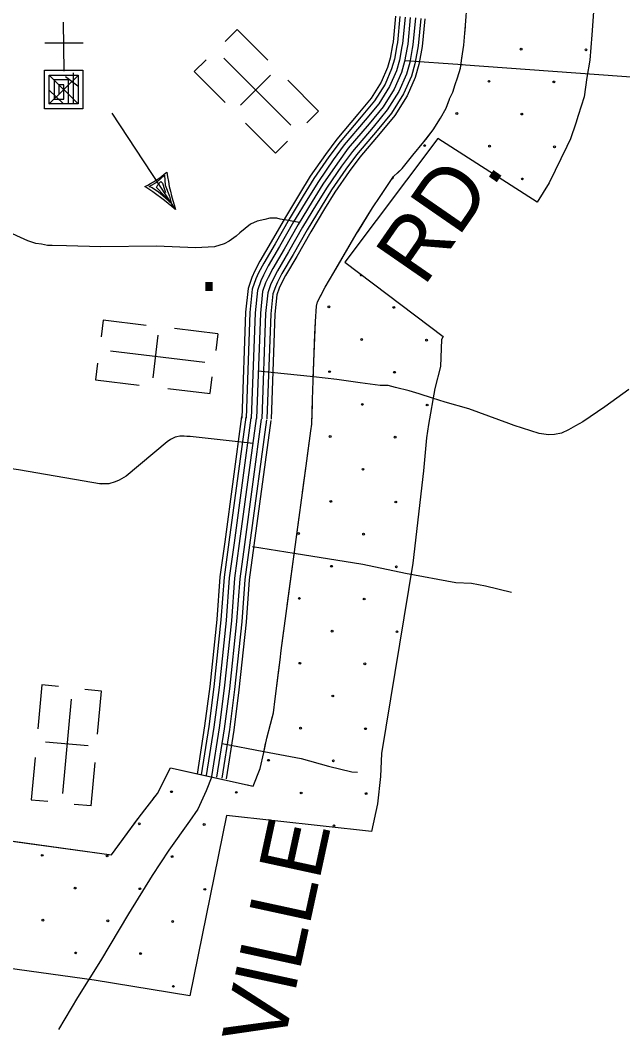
# Model space of a CAD drawing. Extents: x 1788175 to 1969470, y 584502 to 738744.
# Drawn here: x 1811675 to 1815246, y 693983 to 699962 of the extents above; entities that cross this region are included whole.
import ezdxf

# ---------------------------------------------------------------- set-up
doc = ezdxf.new("R2010")
doc.units = 0
for name, color, linetype in [('DESIGN - EROSION CONTROL - Devices', 7, 'Continuous'), ('DESIGN - ROW - Right-of-Way and Easement Labels', 7, 'Continuous'), ('DESIGN - SCRATCH - User 1', 7, 'Continuous'), ('DESIGN - UTILITIES - Cable (Overhead) with Text', 7, 'Continuous'), ('DESIGN - UTILITIES - Cable (Underground) with Text', 7, 'Continuous'), ('SURVEY - CONTOURS - Index with Text', 7, 'Continuous'), ('SURVEY - DRAINAGE - Area Shapes', 7, 'Continuous'), ('SURVEY - TRANSPORTATION - Roads', 7, 'Continuous'), ('SURVEY - VEGETATION - Features with Text', 7, 'Continuous')]:
    doc.layers.add(name, color=color, linetype=linetype)

msp = doc.modelspace()

# ---------------------------------------------------------------- linework, layer by layer
at = {"layer": 'DESIGN - EROSION CONTROL - Devices'}
for centre in [(1814643.4, 699790.1), (1815027.9, 699786.4), (1814453, 699599.7), (1814837.5, 699596), (1814262.6, 699409.3), (1814647.1, 699405.6), (1814072.1, 699218.9), (1814456.7, 699215.2), (1814841.2, 699211.4), (1814650.8, 699021), (1813504.6, 698263.1), (1813889.2, 698259.4), (1813698.8, 698069), (1814083.3, 698065.2), (1813508.4, 697878.6), (1813892.9, 697874.8), (1813702.5, 697684.4), (1814087.1, 697680.7), (1813512.1, 697494), (1813896.7, 697490.3), (1813706.3, 697299.9), (1813515.8, 697109.4), (1813900.4, 697105.7), (1813325.4, 696919), (1813710, 696915.3), (1813519.6, 696724.9), (1813904.1, 696721.2), (1813329.2, 696534.5), (1813713.7, 696530.7), (1813523.3, 696340.3), (1813907.9, 696336.6), (1813332.9, 696149.9), (1813717.5, 696146.2), (1813527, 695955.8), (1813336.6, 695765.4), (1813721.2, 695761.6), (1813146.2, 695575), (1813530.8, 695571.2), (1812571.3, 695388.3), (1812955.8, 695384.6), (1813340.4, 695380.8), (1813724.9, 695377.1), (1812380.9, 695197.9), (1812765.4, 695194.1), (1813534.5, 695186.7), (1811805.9, 695011.2), (1812190.4, 695007.5), (1812575, 695003.7), (1812000, 694817.1), (1812384.6, 694813.3), (1812769.1, 694809.6), (1811809.6, 694626.7), (1812194.2, 694622.9), (1812578.7, 694619.2), (1812003.8, 694432.5), (1812388.3, 694428.8), (1812582.5, 694234.6)]:
    msp.add_circle(centre, 5.28, dxfattribs=at)
for centre, start, end in [((1813881.7, 699028.5), 254.8969, 37.81057), ((1813695.1, 698453.5), 120.83352, 344.928)]:
    msp.add_arc(centre, 5.28, start, end, dxfattribs=at)
at = {"layer": 'DESIGN - SCRATCH - User 1'}
msp.add_line((1809300.4, 695418.4), (1812216, 695014.2), dxfattribs=at)
for points in [[(1815369, 701743.3), (1815264.3, 700905.2), (1815261.1, 700870.7), (1815251.2, 700791.2), (1815242.8, 700757.6), (1815233.4, 700694.9), (1815204.5, 700579.1), (1815178.4, 700505.3), (1815169.6, 700477.5), (1815155.2, 700419.7), (1815127.3, 700326.5), (1815107.1, 700282.1), (1815106.4, 700280), (1815085.9, 700223.9), (1815071.8, 700012), (1815062.1, 699875.7), (1815050.2, 699725.5), (1815033.7, 699622.4), (1815016.6, 699507.8), (1814981.7, 699397.5), (1814967.5, 699351.3), (1814936.8, 699259.2), (1814915.1, 699214.1)], [(1814219.1, 699493.5), (1814220.1, 699495.9), (1814238.4, 699535.7), (1814253.2, 699580.2), (1814265.7, 699620.7), (1814283.6, 699677.4), (1814292.6, 699737.3), (1814304.9, 699814.4), (1814314.2, 699931.9), (1814323.6, 700063.6)], [(1813056.4, 695421.8), (1813096.2, 695525.2), (1813117.9, 695620.6), (1813136.1, 695705.5), (1813157.6, 695787.9), (1813175.3, 695856.5), (1813186.4, 695938.4), (1813214.8, 696169.4), (1813221.1, 696225.9), (1813300, 696809.9), (1813369.2, 697320.9), (1813396.6, 697526.9), (1813402.9, 697567.7), (1813407.6, 697713.7), (1813411.6, 697824), (1813415.8, 697936.9), (1813424.6, 698175), (1813431, 698266.5), (1813437.3, 698291.6), (1813483, 698379.1), (1813534.2, 698466.3), (1813666.5, 698693.6), (1813763, 698849.6), (1813809.1, 698916.3), (1813887.8, 699034.6), (1813939.4, 699082.8), (1814002.8, 699162.4), (1814067.5, 699240.1), (1814121.8, 699311.7), (1814166.2, 699382.1), (1814199.7, 699441.4), (1814219.1, 699493.5)], [(1814915.1, 699214.1), (1814810.2, 698997.2), (1814738.9, 698884.3), (1814150.1, 699260.1), (1813599.6, 698528.2), (1814181.6, 698087.7), (1814171.2, 698070), (1814165.3, 697909.3), (1814131.5, 697778.8), (1814095.3, 697565.2), (1814083.3, 697487.1), (1814064.9, 697289.7), (1814002.2, 696744), (1813816.2, 695614.4), (1813809.5, 695478), (1813792.6, 695316), (1813756.4, 695152.5)], [(1812216, 695014.2), (1812379.1, 695238), (1812488.9, 695378.4), (1812566, 695529), (1813056.4, 695421.8)], [(1813756.4, 695152.5), (1812898.1, 695247.4), (1812680, 694178.7), (1812113, 694271.3), (1809243.5, 694669.1)]]:
    msp.add_lwpolyline(points, dxfattribs=at)
at = {"layer": 'DESIGN - UTILITIES - Cable (Overhead) with Text'}
for p, q in [((1812596, 698839.3), (1812219.4, 699410.6)), ((1812484, 699001.6), (1812530.9, 699044)), ((1812530.9, 699044), (1812533.8, 698983.8)), ((1812438.3, 698976.6), (1812484, 699001.6)), ((1812457.1, 698967.4), (1812438.3, 698976.6)), ((1812493.9, 698942.3), (1812457.1, 698967.4)), ((1812482.9, 698970.5), (1812490.6, 698985.7)), ((1812568.8, 698878.7), (1812482.9, 698970.5)), ((1812490.6, 698985.7), (1812508.7, 699006.5)), ((1812508.7, 699006.5), (1812518.6, 698995.3)), ((1812518.6, 698995.3), (1812528.1, 698963.5)), ((1812528.1, 698963.5), (1812536.3, 698939.7)), ((1812533.8, 698983.8), (1812559.3, 698918.1)), ((1812534.6, 698909.5), (1812493.9, 698942.3)), ((1812576.7, 698868.7), (1812534.6, 698909.5)), ((1812559.3, 698918.1), (1812568.8, 698878.7))]:
    msp.add_line(p, q, dxfattribs=at)
for centre, radius, start, end in [((1812188.2, 699457.9), 532.3, 294.95936, 311.81775), ((1813913.7, 699270.2), 1386.4, 188.66782, 198.10636), ((1811581.2, 697664.7), 1552.3, 49.17613, 57.60391)]:
    msp.add_arc(centre, radius, start, end, dxfattribs=at)
at = {"layer": 'DESIGN - UTILITIES - Cable (Underground) with Text'}
for p, q in [((1812960.4, 699906.8), (1812889.9, 699836.3)), ((1813141.8, 699725.2), (1812960.3, 699906.7)), ((1812048.8, 699825.8), (1811820.7, 699825.8)), ((1812776.1, 699728.1), (1812706, 699658.1)), ((1812705.6, 699657.6), (1812890, 699473.2)), ((1813159.1, 699637.2), (1812979.7, 699457.9)), ((1813443.4, 699423.6), (1813260.9, 699606.1)), ((1813443.3, 699423.5), (1813373, 699353.1)), ((1813010.9, 699352.3), (1813188.7, 699174.5)), ((1813188.8, 699174.6), (1813258.3, 699244.1)), ((1812167.1, 698183.2), (1812155.5, 698084.1)), ((1812422.1, 698153.1), (1812167.1, 698183.1)), ((1812845.7, 698103.4), (1812589.3, 698133.5)), ((1812490.2, 698094.8), (1812460.6, 697842.9)), ((1812845.7, 698103.2), (1812834.1, 698004.4)), ((1812133.3, 697928.7), (1812121.7, 697830.3)), ((1812121.6, 697829.7), (1812380.7, 697799.3)), ((1812800.2, 697750.1), (1812811.7, 697847.7)), ((1812550.4, 697779.3), (1812800.2, 697750)), ((1811802.4, 696021.1), (1811778.8, 695761.3)), ((1811901.7, 696012.1), (1811803, 696021.1)), ((1812157, 695984.9), (1812057.6, 695993.9)), ((1812133.6, 695729.2), (1812156.9, 695984.9)), ((1812077, 695659.7), (1811824.5, 695682.6)), ((1811763.3, 695591.1), (1811740.5, 695340.7)), ((1812095, 695304.5), (1812118.4, 695561.5)), ((1811740.7, 695340.7), (1811838.5, 695331.8)), ((1812094.8, 695304.5), (1811995.7, 695313.5))]:
    msp.add_line(p, q, dxfattribs=at)
for points in [[(1811930.3, 699949.7), (1811932.8, 699659.2)], [(1812881.2, 699737.9), (1813279.3, 699339.8)], [(1811932.7, 699670.1), (1811932.8, 699665.1), (1812046.8, 699665.1), (1812046.8, 699437), (1811818.7, 699437), (1811818.7, 699665.1), (1811989.8, 699665.1), (1811989.8, 699661)], [(1812020.1, 699636.6), (1811845.1, 699464.6)], [(1811989.8, 699650.9), (1811989.8, 699465.5), (1811847.2, 699465.5), (1811847.2, 699636.6), (1812018.3, 699636.6), (1812018.3, 699465.5), (1811961.3, 699465.5), (1811961.3, 699608.1), (1811875.7, 699608.1), (1811875.7, 699494), (1811932.8, 699494), (1811932.8, 699579.5), (1811904.3, 699579.5), (1811904.3, 699522.5)], [(1811848, 699633.7), (1812017.2, 699467.5)], [(1811944.3, 699627.9), (1812017.2, 699572.5)], [(1811848, 699546.2), (1811929.7, 699467.5)], [(1812209.7, 698001.5), (1812768.9, 697935.8)], [(1811976.5, 695937.6), (1811925.5, 695376.9)]]:
    msp.add_lwpolyline(points, dxfattribs=at)
at = {"layer": 'SURVEY - CONTOURS - Index with Text'}
for points in [[(1813899.7, 699986.1), (1813885, 699833.1), (1813881.5, 699816.6), (1813867.5, 699737.5), (1813851.8, 699681.5), (1813814.1, 699595.3), (1813754, 699500), (1813675.2, 699405), (1813550.5, 699257.6), (1813483.3, 699166.5), (1813394.3, 699037.8), (1813330.2, 698933.7), (1813246.4, 698794.8), (1813163.1, 698648.6), (1813095.5, 698533.6), (1813064.8, 698475.4), (1813048, 698437.6), (1813025, 698372.4), (1813010.6, 698231), (1812987.5, 697603.8)], [(1813925.3, 699983.8), (1813910.4, 699829.2), (1813906.8, 699811.7), (1813892.6, 699731.8), (1813876, 699672.8), (1813836.9, 699583.2), (1813774.8, 699484.8), (1813694.9, 699388.5), (1813570.7, 699241.7), (1813504.2, 699151.5), (1813415.9, 699023.8), (1813352.1, 698920.4), (1813268.6, 698781.7), (1813185.3, 698635.7), (1813118, 698521.1), (1813088, 698464.1), (1813071.9, 698428.1), (1813050.2, 698366.8), (1813036.3, 698229.3), (1813013.2, 697602.8)], [(1813956.2, 699980.9), (1813941.1, 699824.6), (1813937.2, 699805.8), (1813922.8, 699724.8), (1813905.3, 699662.4), (1813864.4, 699568.6), (1813800, 699466.6), (1813718.6, 699368.6), (1813595, 699222.5), (1813529.5, 699133.5), (1813441.8, 699006.8), (1813378.6, 698904.2), (1813295.3, 698766.1), (1813212.2, 698620.2), (1813145.1, 698506), (1813115.9, 698450.6), (1813100.7, 698416.6), (1813080.7, 698359.9), (1813067.3, 698227.1), (1813044.2, 697601.7)], [(1813987, 699978.1), (1813971.8, 699820), (1813967.7, 699800), (1813953.1, 699717.9), (1813934.6, 699651.9), (1813891.9, 699554.1), (1813825.1, 699448.3), (1813742.4, 699348.7), (1813619.3, 699203.2), (1813554.7, 699115.5), (1813467.8, 698989.8), (1813405.1, 698888.1), (1813322.1, 698750.4), (1813239, 698604.7), (1813172.2, 698490.9), (1813143.8, 698437), (1813129.5, 698405.1), (1813111.2, 698353.1), (1813098.2, 698225), (1813075.2, 697600.5)], [(1813987, 699978.1), (1813971.8, 699820), (1813967.7, 699800), (1813953.1, 699717.9), (1813934.6, 699651.9), (1813891.9, 699554.1), (1813825.1, 699448.3), (1813742.4, 699348.7), (1813619.3, 699203.2), (1813554.7, 699115.5), (1813467.8, 698989.8), (1813405.1, 698888.1), (1813322.1, 698750.4), (1813239, 698604.7), (1813172.2, 698490.9), (1813143.8, 698437), (1813129.5, 698405.1), (1813111.2, 698353.1), (1813098.2, 698225), (1813075.2, 697600.5)], [(1814017.9, 699975.3), (1814002.5, 699815.3), (1813998.1, 699794.1), (1813983.3, 699711), (1813963.9, 699641.5), (1813919.3, 699539.5), (1813850.2, 699430.1), (1813766.1, 699328.8), (1813643.7, 699184), (1813579.9, 699097.5), (1813493.8, 698972.9), (1813431.5, 698871.9), (1813348.8, 698734.7), (1813265.8, 698589.2), (1813199.3, 698475.8), (1813171.7, 698423.5), (1813158.4, 698393.6), (1813141.6, 698346.3), (1813129.1, 698222.9), (1813106.2, 697599.4)], [(1814048.8, 699972.4), (1814033.2, 699810.7), (1814028.6, 699788.2), (1814013.6, 699704.1), (1813993.1, 699631.1), (1813946.8, 699525), (1813875.4, 699411.8), (1813789.9, 699308.9), (1813668, 699164.8), (1813605.2, 699079.5), (1813519.7, 698955.9), (1813458, 698855.8), (1813375.6, 698719), (1813292.7, 698573.6), (1813226.4, 698460.8), (1813199.6, 698409.9), (1813187.2, 698382.1), (1813172.1, 698339.4), (1813160.1, 698220.7), (1813137.1, 697598.2)], [(1814073.4, 699970.1), (1814057.7, 699807), (1814052.8, 699783.5), (1814037.7, 699698.6), (1814016.5, 699622.8), (1813968.7, 699513.3), (1813895.4, 699397.3), (1813808.9, 699293), (1813687.4, 699149.4), (1813625.3, 699065.1), (1813540.4, 698942.4), (1813479.1, 698842.9), (1813396.9, 698706.5), (1813314.1, 698561.2), (1813248, 698448.7), (1813221.8, 698399.1), (1813210.2, 698372.9), (1813196.4, 698334), (1813184.8, 698219), (1813161.8, 697597.3)], [(1812724.9, 695492.7), (1812770.1, 695778.4), (1812800.1, 696012), (1812842.1, 696408.9), (1812860.8, 696662.6), (1812888.9, 696870.5), (1812989.3, 697612.2)], [(1812749.3, 695488.8), (1812794.6, 695774.9), (1812824.6, 696009.2), (1812866.8, 696406.7), (1812885.4, 696660.1), (1812913.4, 696867.2), (1813013.7, 697608.8)], [(1812779.9, 695483.9), (1812825.3, 695770.5), (1812855.4, 696005.6), (1812897.6, 696403.9), (1812916.2, 696656.9), (1812944.1, 696863.1), (1813044.5, 697604.7)], [(1812810.5, 695479.1), (1812856, 695766.1), (1812886.2, 696002), (1812928.5, 696401.1), (1812947.1, 696653.7), (1812974.8, 696858.9), (1813075.2, 697600.5)], [(1812810.5, 695479.1), (1812856, 695766.1), (1812886.2, 696002), (1812928.5, 696401.1), (1812947.1, 696653.7), (1812974.8, 696858.9), (1813075.2, 697600.5)], [(1812841.2, 695474.2), (1812886.7, 695761.7), (1812917, 695998.4), (1812959.4, 696398.4), (1812977.9, 696650.4), (1813005.5, 696854.7), (1813105.9, 697596.4)], [(1812871.8, 695469.4), (1812917.4, 695757.3), (1812947.8, 695994.7), (1812990.3, 696395.6), (1813008.8, 696647.2), (1813036.2, 696850.6), (1813136.6, 697592.2)], [(1812897.2, 695465.4), (1812942.8, 695753.6), (1812973.3, 695991.8), (1813015.9, 696393.3), (1813034.4, 696644.6), (1813061.7, 696847.1), (1813162.1, 697588.8)], [(1812810.5, 695479.1), (1812777.6, 695393.5), (1812726.9, 695285.6), (1812679, 695213.9), (1812555, 695042.3), (1812456.8, 694892.6), (1812316.4, 694665.1), (1812150, 694385.6), (1812014.2, 694168.9), (1811901.3, 693978.5)]]:
    msp.add_lwpolyline(points, dxfattribs=at)
at = {"layer": 'SURVEY - DRAINAGE - Area Shapes'}
for points in [[(1814286.5, 699699.4), (1815785.9, 699590.2)], [(1814571.2, 697570.8), (1814333.7, 697658.2), (1814194.4, 697698.4), (1814118.8, 697721.5), (1814039.2, 697746.8), (1813979.5, 697765.7), (1813899.9, 697784.9), (1813856.1, 697795.6), (1813808.1, 697796.3), (1813690.4, 697812.1), (1813550.8, 697832.2), (1813412.5, 697847.1)], [(1815282.4, 697773.3), (1815138.8, 697669.3), (1815009.5, 697581), (1814965.1, 697557.7), (1814924.8, 697534.2), (1814882.5, 697514.8), (1814842.3, 697505.4), (1814806.3, 697503.9), (1814750.5, 697512.8), (1814603.3, 697559), (1814571.2, 697570.8)], [(1813298.9, 696801.9), (1813704.6, 696737.5), (1813958.3, 696683.3), (1814256.1, 696629.1), (1814350, 696625), (1814431.9, 696608.9), (1814587.1, 696570.6)], [(1813119.3, 695627.1), (1813340.8, 695585.2), (1813502.6, 695539.1), (1813640.5, 695507), (1813673.1, 695504.6)]]:
    msp.add_lwpolyline(points, dxfattribs=at)
at = {"layer": 'SURVEY - TRANSPORTATION - Roads'}
for points in [[(1813954.1, 699723.6), (1814295.8, 699698.7)], [(1813328.9, 698762.3), (1813254, 698776.3), (1813216.2, 698782.8), (1813195.3, 698787.7), (1813154.3, 698787.8), (1813124.2, 698780.2), (1813080, 698770.8), (1813039.8, 698753.4), (1812977, 698702.2), (1812954.7, 698682.5), (1812914.2, 698653.1), (1812884, 698635.5), (1812825.9, 698617.9), (1812713.7, 698612), (1812481.9, 698623.4), (1812152, 698618.3), (1811948.5, 698623.8), (1811864.3, 698626.6), (1811836.3, 698627), (1811800.4, 698633.6), (1811768.5, 698638), (1811720.8, 698654.8), (1811448.9, 698777)], [(1813412.5, 697847.1), (1813085.6, 697882.2)], [(1812157.3, 697211.5), (1811664.8, 697297.1), (1811351.1, 697341.4), (1811027.4, 697383.6), (1810771.6, 697425.9), (1810671.7, 697451.9), (1810625.8, 697476), (1810615, 697486.8)], [(1813055.3, 697453.6), (1812681.7, 697493.7), (1812661.6, 697494.8), (1812646, 697495.9), (1812620.4, 697495.9), (1812603.7, 697491.5), (1812592.6, 697489.3), (1812565.8, 697475.9), (1812546.9, 697462.5), (1812302.8, 697259.7), (1812260.5, 697235.2), (1812238.2, 697225.2), (1812200, 697214.4), (1812146.6, 697213.4)], [(1813052.2, 696842.8), (1813298.9, 696801.9)], [(1812872.7, 695673.7), (1813119.3, 695627.1)]]:
    msp.add_lwpolyline(points, dxfattribs=at)
at = {"layer": 'SURVEY - VEGETATION - Features with Text'}
for points in [[(1814311.2, 699894.3), (1814314.2, 699931.9), (1814323.6, 700063.6), (1814329.9, 700157.7)], [(1814219.1, 699493.5), (1814220.1, 699495.9), (1814238.4, 699535.7), (1814253.2, 699580.2), (1814265.7, 699620.7), (1814283.6, 699677.4), (1814292.6, 699737.3), (1814304.9, 699814.4), (1814314.2, 699931.9), (1814323.6, 700063.6)], [(1814219.1, 699493.5), (1814220.1, 699495.9), (1814238.4, 699535.7), (1814253.2, 699580.2), (1814265.7, 699620.7), (1814283.6, 699677.4), (1814292.6, 699737.3), (1814293.9, 699745.5)], [(1813056.4, 695421.8), (1813096.2, 695525.2), (1813117.9, 695620.6), (1813136.1, 695705.5), (1813157.6, 695787.9), (1813175.3, 695856.5), (1813186.4, 695938.4), (1813214.8, 696169.4), (1813221.1, 696225.9), (1813300, 696809.9), (1813369.2, 697320.9), (1813396.6, 697526.9), (1813402.9, 697567.7), (1813407.6, 697713.7), (1813411.6, 697824), (1813415.8, 697936.9), (1813424.6, 698175), (1813431, 698266.5), (1813437.3, 698291.6), (1813483, 698379.1), (1813534.2, 698466.3), (1813666.5, 698693.6), (1813763, 698849.6), (1813809.1, 698916.3), (1813887.8, 699034.6), (1813939.4, 699082.8), (1814002.8, 699162.4), (1814067.5, 699240.1), (1814121.8, 699311.7), (1814166.2, 699382.1), (1814199.7, 699441.4), (1814219.1, 699493.5)], [(1814080.8, 699257.7), (1814121.8, 699311.7), (1814166.2, 699382.1), (1814199.7, 699441.4), (1814215.3, 699483.4)], [(1813910.8, 699056.1), (1813939.4, 699082.8), (1814002.8, 699162.4), (1814067.5, 699240.1), (1814080.8, 699257.7)], [(1813679.2, 698714.1), (1813763, 698849.6), (1813809.1, 698916.3), (1813822.2, 698936)], [(1813545.8, 698486.3), (1813666.5, 698693.6), (1813679.2, 698714.1)], [(1813421.9, 698101.6), (1813424.6, 698175), (1813431, 698266.5), (1813437.3, 698291.6), (1813471.1, 698356.3)], [(1813412.1, 697837.8), (1813415.8, 697936.9), (1813421.9, 698101.6)], [(1813383.1, 697425.3), (1813396.6, 697526.9), (1813402.9, 697567.7), (1813406.8, 697687.9)], [(1813347.9, 697163.7), (1813369.2, 697320.9), (1813383.1, 697425.3)], [(1813292.4, 696753.4), (1813300, 696809.9), (1813327.8, 697015)], [(1813257, 696491.8), (1813292.4, 696753.4)], [(1813204, 696081.2), (1813214.8, 696169.4), (1813221.1, 696225.9), (1813237, 696343.2)], [(1813166, 695820.3), (1813175.3, 695856.5), (1813186.4, 695938.4), (1813204, 696081.2)], [(1813056.4, 695421.8), (1813096.2, 695525.2), (1813117.9, 695620.6), (1813129.5, 695674.8)], [(1812216, 695014.2), (1812379.1, 695238), (1812488.9, 695378.4), (1812566, 695529), (1813056.4, 695421.8)], [(1812463.5, 695346), (1812488.9, 695378.4), (1812566, 695529), (1812618.5, 695517.5)], [(1812618.5, 695517.5), (1812876.4, 695461.2)], [(1813022.9, 695429.1), (1813056.4, 695421.8)], [(1809300.4, 695418.4), (1812216, 695014.2)], [(1812216, 695014.2), (1812371.5, 695227.6)], [(1811725.2, 695082.2), (1811986.7, 695046)], [(1811986.7, 695046), (1812216, 695014.2)]]:
    msp.add_lwpolyline(points, dxfattribs=at)

# ---------------------------------------------------------------- texts
at = {"layer": 'DESIGN - ROW - Right-of-Way and Easement Labels'}
for s, rotation, p in [('RD.', 55.32916, (1814067.6, 698377.3)), ('NONAVILLE', 77.74888, (1812927.3, 692463.8))]:
    msp.add_text(s, height=370, rotation=rotation, dxfattribs=at).set_placement(p)
at = {"layer": 'DESIGN - UTILITIES - Cable (Underground) with Text'}
msp.add_text('.', height=343, dxfattribs=at).set_placement((1812730.4, 698356.9))

doc.saveas('drawing.dxf')
